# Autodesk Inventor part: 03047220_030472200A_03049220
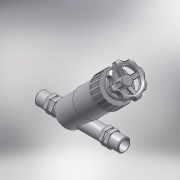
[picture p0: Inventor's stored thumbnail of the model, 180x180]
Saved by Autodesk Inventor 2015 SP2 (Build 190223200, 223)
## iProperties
Created: 2017-05
Part Number: 03047220_030472200A_03049220
Material: Generic
Description: PLASSON ANGLE SEAT VALVE 2"-2"
Document SubType Name: Modeling
Designer: KIM
Mass: 184.302 g
Surface Area: 375.869 cm^2
Volume: 184.302 cm^3
Density: 1 g/cm^3
Appearance: Default
Author: KIM
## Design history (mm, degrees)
derived "03047.ipt"
feature "Solid1::03047.ipt"
tag "TaggingFeature1"
body "Solid1"
other parameters: "d0" = 254, "d1" = 59.614, "d2" = 65, "d3" = 47.6912, "d4" = 26, "d5" = 26, "d6" = 25.4, "d8" = 2.54, "d12" = 0, "d14" = -12.7, "d15" = 5.08, "d16" = 0, "d17" = 73.062, "d19" = 232.47, "d20" = 88.56, "d21" = 135 deg, "d22" = 94.095, "d23" = 44.28, "d24" = 105.165, "d25" = 26.568, "d26" = 90 deg, "d27" = 77.49, "d28" = 70 deg, "d29" = 33.21, "d30" = 26.568, "d31" = 33.21, "d32" = 110.7, "d33" = 77.49, "d34" = 135 deg, "d35" = 2, "d36" = 221.4, "d39" = 88.9, "d40" = 2.46, "d42" = 2, "d43" = 7.38, "d44" = 7.38, "d46" = 0, "d48" = 360 deg, "d50" = 1.23, "d51" = 1.23, "d53" = 360 deg, "d69" = 94.095, "d70" = 7.38, "d71" = 7.38, "d72" = 14.76, "d74" = 0, "d75" = 1.23, "d77" = 360 deg, "d80" = 102.01005, "d81" = 9.84, "d82" = 4.92, "d83" = 39.852, "d84" = 0, "d86" = 360 deg, "d88" = 2.46, "d89" = 8.856, "d90" = 1.23, "d91" = 246, "H_" = 254, "R_" = 59.614, "E_" = 65, "l_2" = 26, "A_" = 246, "d13" = 25.4, "d67" = 110.7, "d68" = 77.49, "d79" = 105.165
